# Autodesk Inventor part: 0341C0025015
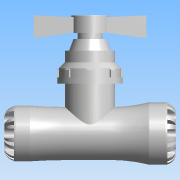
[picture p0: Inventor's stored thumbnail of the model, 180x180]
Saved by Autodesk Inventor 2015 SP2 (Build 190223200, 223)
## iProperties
Created: 2016-12
Part Number: 0341C0025015
Material: PVC-Piping
Description: PLASSON COPPER PIPE ADAPTOR STOPTAP 25-15 SERIES 1
Document SubType Name: Modeling
Designer: KIM
Mass: 61.7504 g
Surface Area: 140.097 cm^2
Volume: 44.1074 cm^3
Density: 1.4 g/cm^3
Appearance: Smooth - White
Author: KIM
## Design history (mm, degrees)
derived "0341C.ipt"
feature "Solid1::0341C.ipt"
feature "Solid2::0341C.ipt"
tag "TaggingFeature1"
body "Solid1"
other parameters: "d1" = 20.16, "d2" = 25, "d3" = 31.25, "d4" = 47, "d6" = 48, "d8" = 39.95, "d13" = 6.3, "d14" = 6.3, "d15" = 0, "d17" = 360 deg, "d19" = 8 deg, "d20" = 0.5, "d21" = 0.5, "d22" = 8 deg, "d24" = 0, "d26" = 360 deg, "d33" = 4.7, "d35" = 3.125, "d65" = 0.47, "d69" = 129, "d71" = 15, "d72" = 42, "d73" = 24, "d74" = 19.32, "d75" = 64.5, "d76" = 1.875, "d77" = 46, "d80" = 7.2, "d82" = 7.2, "d83" = 0, "d85" = 360 deg, "d87" = 0.3, "d88" = 8 deg, "d89" = 8 deg, "d90" = 0.3, "d92" = 0, "d94" = 360 deg, "d96" = 89, "d97" = 47, "d98" = 37.6, "d99" = 37.6, "d100" = 135 deg, "d101" = 18.8, "d102" = 70 deg, "d103" = 48.95, "d104" = 71.2, "d105" = 62.3, "d107" = 75.65, "d108" = 84.6, "d110" = 12.015, "d111" = 4.005, "d112" = 14.1, "d113" = 0, "d114" = 49.35, "d115" = 4.7, "d116" = 0, "d117" = 4.7, "d119" = 0, "d121" = 360 deg, "d127" = 0, "d128" = 0.47, "d_" = 25, "E_" = 47, "H_" = 129, "l_" = 48, "A_" = 89, "l_1" = 46, "d_1" = 15, "E_1" = 42, "d9" = 7.875, "d11" = 47, "d12" = 31.25, "d78" = 42, "d79" = 24, "d81" = 9, "d109" = 13.35
